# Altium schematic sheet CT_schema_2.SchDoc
size 282 x 169 mm
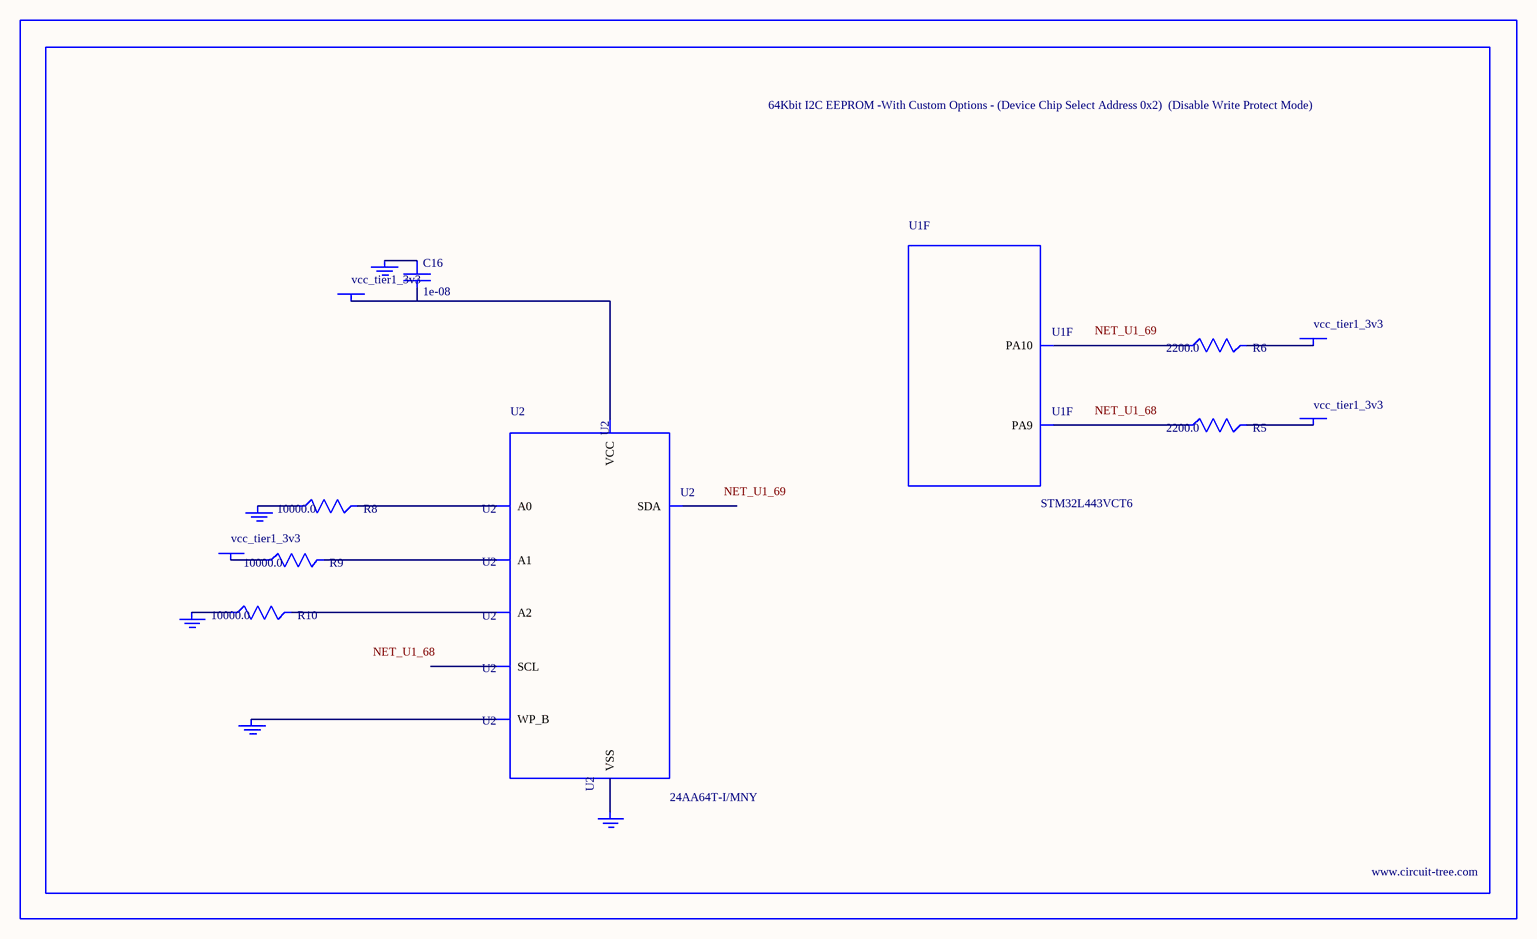
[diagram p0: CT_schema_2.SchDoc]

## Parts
BORDER1  (no value)
C16  1e-08  [C0402]
GND_INSTANCE_1_0  (no value)
GND_INSTANCE_1_1  (no value)
GND_INSTANCE_1_2  (no value)
GND_INSTANCE_1_3  (no value)
GND_INSTANCE_1_4  (no value)
POWER_INSTANCE_1_0  vcc_tier1_3v3
POWER_INSTANCE_1_1  vcc_tier1_3v3
POWER_INSTANCE_1_2  vcc_tier1_3v3
POWER_INSTANCE_1_3  vcc_tier1_3v3
R5  2200.0  [R0603]
R6  2200.0  [R0603]
R8  10000.0  [R0603]
R9  10000.0  [R0603]
R10  10000.0  [R0603]
U1  STM32L443VCT6  [LQFP100]  (part F of 9)
U2  24AA64T-I/MNY  [TDFN-8/6MM]

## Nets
NetC16_1: C16.1 GND_INSTANCE_1_3.0(GND)
NetC16_2: C16.2 POWER_INSTANCE_1_1.0(PWR) U2.8(VCC)
NetGND_INSTANCE_1_0_0: GND_INSTANCE_1_0.0(GND) R8.1
NetGND_INSTANCE_1_1_0: GND_INSTANCE_1_1.0(GND) R10.1
NetGND_INSTANCE_1_2_0: GND_INSTANCE_1_2.0(GND) U2.7(WP_B)
NetGND_INSTANCE_1_4_0: GND_INSTANCE_1_4.0(GND) U2.4(VSS)
NetPOWER_INSTANCE_1_0_0: POWER_INSTANCE_1_0.0(PWR) R9.1
NetPOWER_INSTANCE_1_2_0: POWER_INSTANCE_1_2.0(PWR) R5.2
NetPOWER_INSTANCE_1_3_0: POWER_INSTANCE_1_3.0(PWR) R6.2
NetR5_1: R5.1 U1.68(PA9)
NetR6_1: R6.1 U1.69(PA10)
NetR8_2: R8.2 U2.1(A0)
NetR9_2: R9.2 U2.2(A1)
NetR10_2: R10.2 U2.3(A2)

Not connected (* = marked no-connect by the designer): U2 5(SDA) 6(SCL)

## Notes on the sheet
- Labels drawn without touching a wire or pin: NET_U1_68, NET_U1_69

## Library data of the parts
BORDER1 = BORDER_PAGE1
C16 = C0402C103K3RAC
GND_INSTANCE_1_0-GND_INSTANCE_1_4 = GND
POWER_INSTANCE_1_0-POWER_INSTANCE_1_3 = PWR
R5 R6 = RC0603JR-072K2L
R8-R10 = RC0603JR-0710KL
